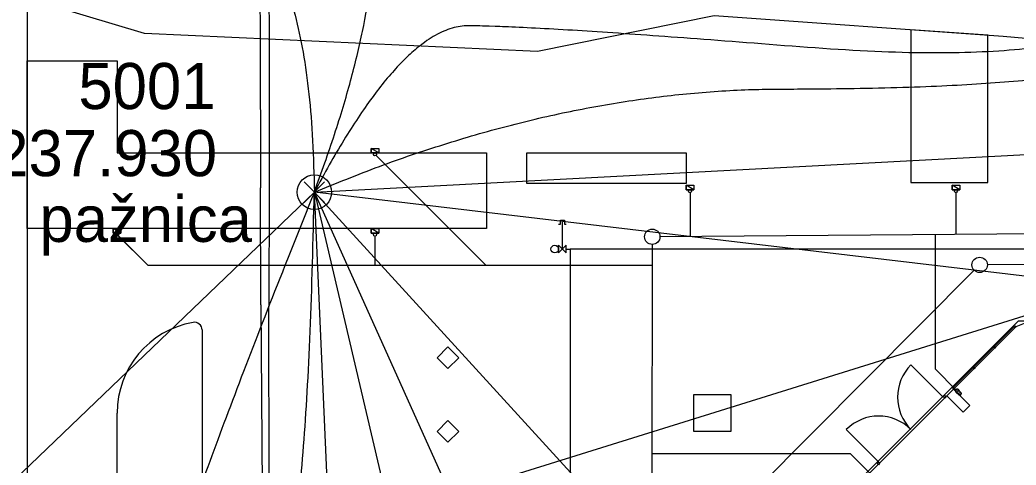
# Model space of a CAD drawing. Extents: x -264090 to -263500, y -1242327 to -1242030.
# Drawn here: x -263959.9 to -263895.1, y -1242096.7 to -1242067.7 of the extents above; entities that cross this region are included whole.
import ezdxf

# ---------------------------------------------------------------- set-up
doc = ezdxf.new("R2010")
doc.units = 0
for name, color, linetype in [('KFA_KOORD_SIT_a_IS_SEDA', 7, 'Continuous'), ('KFA_ZVS_BOD_CISLO', 7, 'Continuous'), ('KFA_ZVS_BOD_SYMBOL', 7, 'Continuous'), ('KFA_ZVS_BOD_VYSKA', 7, 'Continuous'), ('KFA_ZVS_NIVELACIA', 7, 'Continuous'), ('KFA_ZVS_POPIS', 7, 'Continuous'), ('KFA_ZVS_SMERY_A_DLZKY', 7, 'Continuous')]:
    doc.layers.add(name, color=color, linetype=linetype)

msp = doc.modelspace()

# ---------------------------------------------------------------- linework, layer by layer
at = {"layer": 'KFA_KOORD_SIT_a_IS_SEDA'}
for p, q in [((-263959.468, -1242059.534), (-263959.468, -1242179.482)), ((-263944.335, -1242065.473), (-263944.315, -1242068.492)), ((-263943.761, -1242065.469), (-263943.733, -1242068.48)), ((-263944.315, -1242068.492), (-263944.281, -1242078.658)), ((-263943.733, -1242068.48), (-263943.726, -1242078.708)), ((-263896.968, -1242068.731), (-263901.968, -1242068.376)), ((-263901.968, -1242068.376), (-263901.968, -1242074.382)), ((-263896.968, -1242074.382), (-263896.968, -1242068.731)), ((-263959.468, -1242071.382), (-263959.468, -1242070.382)), ((-263959.468, -1242070.382), (-263953.617, -1242070.382)), ((-263953.617, -1242070.382), (-263953.617, -1242076.382)), ((-263959.468, -1242076.382), (-263959.468, -1242071.382)), ((-263901.968, -1242074.382), (-263901.968, -1242078.308)), ((-263896.968, -1242078.308), (-263896.968, -1242074.382)), ((-263959.468, -1242081.307), (-263959.468, -1242076.382)), ((-263953.617, -1242076.382), (-263929.58, -1242076.382)), ((-263937.093, -1242076.382), (-263937.093, -1242076.092)), ((-263937.093, -1242076.092), (-263936.593, -1242076.092)), ((-263936.593, -1242076.382), (-263937.093, -1242076.092)), ((-263936.593, -1242076.382), (-263937.093, -1242076.092)), ((-263937.093, -1242076.092), (-263937.093, -1242076.382)), ((-263936.593, -1242076.382), (-263937.093, -1242076.382)), ((-263937.093, -1242076.382), (-263936.593, -1242076.382)), ((-263936.772, -1242076.553), (-263929.628, -1242083.697)), ((-263936.593, -1242076.092), (-263936.593, -1242076.382)), ((-263929.58, -1242076.382), (-263929.58, -1242081.307)), ((-263926.968, -1242076.382), (-263921.968, -1242076.382)), ((-263926.968, -1242078.382), (-263926.968, -1242076.382)), ((-263926.968, -1242076.382), (-263926.968, -1242076.382)), ((-263921.968, -1242076.382), (-263916.593, -1242076.382)), ((-263916.593, -1242076.382), (-263916.593, -1242078.382)), ((-263921.968, -1242078.382), (-263926.968, -1242078.382)), ((-263916.593, -1242078.382), (-263921.968, -1242078.382)), ((-263916.593, -1242078.777), (-263916.593, -1242078.487)), ((-263916.593, -1242078.487), (-263916.093, -1242078.487)), ((-263916.093, -1242078.777), (-263916.593, -1242078.487)), ((-263916.093, -1242078.777), (-263916.593, -1242078.487)), ((-263916.593, -1242078.487), (-263916.593, -1242078.777)), ((-263916.093, -1242078.487), (-263916.093, -1242078.777)), ((-263901.968, -1242078.308), (-263896.968, -1242078.308)), ((-263899.296, -1242078.777), (-263899.296, -1242078.487)), ((-263899.296, -1242078.487), (-263898.796, -1242078.487)), ((-263898.796, -1242078.777), (-263899.296, -1242078.487)), ((-263898.796, -1242078.777), (-263899.296, -1242078.487)), ((-263899.296, -1242078.487), (-263899.296, -1242078.777)), ((-263898.796, -1242078.487), (-263898.796, -1242078.777)), ((-263944.262, -1242086.274), (-263944.281, -1242078.658)), ((-263943.726, -1242078.708), (-263943.748, -1242086.382)), ((-263916.093, -1242078.777), (-263916.593, -1242078.777)), ((-263916.593, -1242078.777), (-263916.093, -1242078.777)), ((-263916.343, -1242078.977), (-263916.343, -1242081.82)), ((-263898.796, -1242078.777), (-263899.296, -1242078.777)), ((-263899.296, -1242078.777), (-263898.796, -1242078.777)), ((-263899.046, -1242078.977), (-263899.047, -1242081.696)), ((-263924.893, -1242081.015), (-263924.768, -1242081.015)), ((-263924.768, -1242081.015), (-263924.768, -1242080.765)), ((-263924.768, -1242080.765), (-263924.518, -1242080.765)), ((-263924.643, -1242082.64), (-263924.643, -1242080.89)), ((-263924.518, -1242080.765), (-263924.518, -1242081.015)), ((-263924.518, -1242081.015), (-263924.393, -1242081.015)), ((-263953.617, -1242081.307), (-263959.468, -1242081.307)), ((-263953.868, -1242081.597), (-263953.868, -1242081.307)), ((-263953.868, -1242081.307), (-263953.368, -1242081.307)), ((-263953.368, -1242081.597), (-263953.868, -1242081.307)), ((-263953.368, -1242081.597), (-263953.868, -1242081.307)), ((-263953.868, -1242081.307), (-263953.868, -1242081.597)), ((-263953.368, -1242081.597), (-263953.868, -1242081.597)), ((-263953.868, -1242081.597), (-263953.368, -1242081.597)), ((-263953.618, -1242081.697), (-263951.618, -1242083.697)), ((-263929.58, -1242081.307), (-263953.617, -1242081.307)), ((-263953.368, -1242081.307), (-263953.368, -1242081.597)), ((-263937.093, -1242081.597), (-263937.093, -1242081.307)), ((-263937.093, -1242081.307), (-263936.593, -1242081.307)), ((-263936.593, -1242081.597), (-263937.093, -1242081.307)), ((-263936.593, -1242081.597), (-263937.093, -1242081.307)), ((-263937.093, -1242081.307), (-263937.093, -1242081.597)), ((-263936.593, -1242081.597), (-263937.093, -1242081.597)), ((-263937.093, -1242081.597), (-263936.593, -1242081.597)), ((-263936.593, -1242081.307), (-263936.593, -1242081.597)), ((-263872.456, -1242081.505), (-263918.302, -1242081.834)), ((-263900.379, -1242090.456), (-263900.379, -1242081.705)), ((-263953.547, -1242081.768), (-263951.618, -1242083.697)), ((-263936.843, -1242081.797), (-263936.843, -1242083.697)), ((-263924.393, -1242082.39), (-263924.893, -1242082.89)), ((-263924.893, -1242082.89), (-263924.893, -1242082.39)), ((-263924.893, -1242082.39), (-263924.393, -1242082.89)), ((-263924.393, -1242082.89), (-263924.393, -1242082.39)), ((-263918.803, -1242082.338), (-263918.855, -1242106.583)), ((-263924.393, -1242082.64), (-263924.143, -1242082.64)), ((-263788.143, -1242082.64), (-263924.143, -1242082.64)), ((-263924.143, -1242082.64), (-263924.143, -1242185.14)), ((-263853.342, -1242083.478), (-263897, -1242083.666)), ((-263951.618, -1242083.697), (-263918.806, -1242083.697)), ((-263897.853, -1242084.022), (-263922.202, -1242108.463)), ((-263944.262, -1242086.274), (-263944.165, -1242100.884)), ((-263943.732, -1242100.264), (-263943.748, -1242086.382)), ((-263895.135, -1242087.687), (-263894.581, -1242087.457)), ((-263948.093, -1242087.901), (-263948.093, -1242241.458)), ((-263908.663, -1242101.215), (-263895.135, -1242087.687)), ((-263895.258, -1242087.647), (-263896.566, -1242088.955)), ((-263896.548, -1242088.973), (-263895.24, -1242087.665)), ((-263895.273, -1242087.698), (-263895.245, -1242087.67)), ((-263895.202, -1242087.769), (-263895.273, -1242087.698)), ((-263895.24, -1242087.665), (-263895.258, -1242087.647)), ((-263895.245, -1242087.67), (-263895.216, -1242087.641)), ((-263895.216, -1242087.641), (-263895.146, -1242087.712)), ((-263895.146, -1242087.712), (-263895.202, -1242087.769)), ((-263932.8, -1242089.707), (-263932.093, -1242089)), ((-263932.093, -1242089), (-263931.386, -1242089.707)), ((-263932.093, -1242089), (-263932.093, -1242089)), ((-263897.906, -1242090.295), (-263896.598, -1242088.987)), ((-263896.58, -1242089.005), (-263897.888, -1242090.313)), ((-263896.598, -1242088.987), (-263896.58, -1242089.005)), ((-263896.592, -1242089.017), (-263896.564, -1242088.989)), ((-263896.522, -1242089.088), (-263896.592, -1242089.017)), ((-263896.566, -1242088.955), (-263896.548, -1242088.973)), ((-263896.564, -1242088.989), (-263896.536, -1242088.96)), ((-263896.536, -1242088.96), (-263896.465, -1242089.031)), ((-263896.465, -1242089.031), (-263896.522, -1242089.088)), ((-263932.093, -1242090.414), (-263932.8, -1242089.707)), ((-263931.386, -1242089.707), (-263932.093, -1242090.414)), ((-263899.866, -1242092.276), (-263901.97, -1242090.173)), ((-263899.018, -1242091.817), (-263900.379, -1242090.456)), ((-263899.25, -1242091.639), (-263897.942, -1242090.331)), ((-263897.924, -1242090.349), (-263899.232, -1242091.657)), ((-263897.942, -1242090.331), (-263897.924, -1242090.349)), ((-263897.936, -1242090.361), (-263897.908, -1242090.333)), ((-263897.865, -1242090.432), (-263897.936, -1242090.361)), ((-263897.908, -1242090.333), (-263897.88, -1242090.304)), ((-263897.888, -1242090.313), (-263897.906, -1242090.295)), ((-263897.88, -1242090.304), (-263897.809, -1242090.375)), ((-263897.809, -1242090.375), (-263897.865, -1242090.432)), ((-263916.093, -1242092.107), (-263913.693, -1242092.107)), ((-263916.093, -1242094.507), (-263916.093, -1242092.107)), ((-263913.693, -1242092.107), (-263913.693, -1242094.507)), ((-263899.207, -1242091.764), (-263899.631, -1242092.188)), ((-263899.255, -1242091.68), (-263899.227, -1242091.652)), ((-263899.185, -1242091.751), (-263899.255, -1242091.68)), ((-263899.232, -1242091.657), (-263899.25, -1242091.639)), ((-263899.227, -1242091.652), (-263899.199, -1242091.624)), ((-263898.147, -1242092.824), (-263899.207, -1242091.764)), ((-263899.199, -1242091.624), (-263899.128, -1242091.694)), ((-263899.128, -1242091.694), (-263899.185, -1242091.751)), ((-263898.969, -1242092.031), (-263899.047, -1242091.953)), ((-263899.047, -1242091.953), (-263898.969, -1242092.031)), ((-263898.949, -1242092.031), (-263898.969, -1242092.031)), ((-263898.861, -1242092.119), (-263898.949, -1242092.031)), ((-263898.804, -1242091.866), (-263898.882, -1242091.787)), ((-263898.804, -1242091.885), (-263898.804, -1242091.866)), ((-263898.715, -1242091.974), (-263898.804, -1242091.885)), ((-263899.849, -1242092.259), (-263899.866, -1242092.276)), ((-263899.764, -1242092.174), (-263899.849, -1242092.259)), ((-263899.849, -1242092.259), (-263899.764, -1242092.344)), ((-263899.679, -1242092.259), (-263899.764, -1242092.174)), ((-263899.764, -1242092.344), (-263899.679, -1242092.259)), ((-263899.631, -1242092.188), (-263898.571, -1242093.249)), ((-263953.617, -1242244.458), (-263953.617, -1242093.307)), ((-263898.571, -1242093.249), (-263898.147, -1242092.824)), ((-263932.8, -1242094.507), (-263932.093, -1242093.8)), ((-263932.093, -1242093.8), (-263931.386, -1242094.507)), ((-263932.093, -1242093.8), (-263932.093, -1242093.8)), ((-263932.093, -1242095.214), (-263932.8, -1242094.507)), ((-263931.386, -1242094.507), (-263932.093, -1242095.214)), ((-263913.693, -1242094.507), (-263916.093, -1242094.507)), ((-263904.074, -1242096.484), (-263906.177, -1242094.38)), ((-263905.894, -1242095.971), (-263918.832, -1242095.971)), ((-263904.533, -1242097.332), (-263905.894, -1242095.971)), ((-263904.176, -1242096.586), (-263904.091, -1242096.501)), ((-263904.091, -1242096.671), (-263904.176, -1242096.586)), ((-263904.091, -1242096.501), (-263904.074, -1242096.484)), ((-263904.091, -1242096.501), (-263904.006, -1242096.586)), ((-263904.006, -1242096.586), (-263904.091, -1242096.671))]:
    msp.add_line(p, q, dxfattribs=at)
for points in [[(-263864.521, -1242071.581), (-263895.971, -1242068.802), (-263914.777, -1242067.467), (-263926.271, -1242069.784), (-263951.845, -1242068.605), (-263959.611, -1242066.277)], [(-263794.893, -1242227.382), (-263808.968, -1242241.457), (-263894.968, -1242241.457), (-263909.043, -1242227.382), (-263909.043, -1242196.333), (-263914.143, -1242196.333), (-263914.143, -1242132.433), (-263909.043, -1242132.433), (-263909.043, -1242101.382), (-263894.968, -1242087.307), (-263808.968, -1242087.307), (-263794.893, -1242101.382), (-263794.893, -1242227.382)]]:
    msp.add_lwpolyline(points, dxfattribs=at)
for centre, radius in [((-263936.843, -1242076.482), 0.1), ((-263916.343, -1242078.877), 0.1), ((-263899.046, -1242078.877), 0.1), ((-263953.618, -1242081.697), 0.1), ((-263936.843, -1242081.697), 0.1), ((-263918.802, -1242081.838), 0.5), ((-263925.143, -1242082.64), 0.25), ((-263897.5, -1242083.668), 0.5), ((-263898.965, -1242091.87), 0.075), ((-263898.788, -1242092.047), 0.075)]:
    msp.add_circle(centre, radius, dxfattribs=at)
for centre, radius, start, end in [((-263947.634, -1242093.3), 5.983, 100.0694, 180.06602), ((-263948.593, -1242087.901), 0.5, 0, 100.0694), ((-263899.866, -1242092.276), 2.975, 135.00007, 225.00006), ((-263898.965, -1242091.87), 0.117, 45, 225), ((-263898.788, -1242092.047), 0.103, 225, 45), ((-263904.074, -1242096.484), 2.975, 44.99994, 134.99992)]:
    msp.add_arc(centre, radius, start, end, dxfattribs=at)
at = {"layer": 'KFA_ZVS_BOD_SYMBOL'}
for p, q in [((-263941.451, -1242079.601), (-263940.125, -1242078.275)), ((-263940.125, -1242079.601), (-263941.451, -1242078.275))]:
    msp.add_line(p, q, dxfattribs=at)
msp.add_circle((-263940.788, -1242078.938), 1.125, dxfattribs=at)
at = {"layer": 'KFA_ZVS_NIVELACIA'}
for points in [[(-263940.788, -1242078.938), (-263934.156, -1242061.096), (-263943.396, -1242047.979), (-263966.375, -1242038.897), (-263966.375, -1242044.573)], [(-263966.375, -1242044.573), (-263958.148, -1242047.979), (-263963.822, -1242056.777), (-263950.488, -1242056.777), (-263940.964, -1242064.52), (-263940.788, -1242078.938)], [(-263854.005, -1242074.334), (-263858.192, -1242065.861), (-263863.591, -1242056.689), (-263882.165, -1242064.383), (-263892.212, -1242070.833), (-263926.489, -1242068.112), (-263935.058, -1242068.112), (-263940.788, -1242078.938)], [(-263940.788, -1242078.938), (-263924.876, -1242072.224), (-263895.483, -1242072.224), (-263880.684, -1242069.371), (-263870.098, -1242060.864), (-263861.313, -1242065.002), (-263856.49, -1242070.133), (-263854.005, -1242074.334)], [(-263940.788, -1242078.938), (-263950.124, -1242102.026), (-263955.973, -1242123.929), (-263955.973, -1242134.13), (-263943.376, -1242149.689), (-263946.118, -1242158.004), (-263936.802, -1242167.947)], [(-263936.802, -1242167.947), (-263938.18, -1242161.645), (-263941.069, -1242151.603), (-263943.851, -1242126.263), (-263950.707, -1242125.062), (-263946.422, -1242113.061), (-263941.281, -1242104.232), (-263940.788, -1242078.938)]]:
    msp.add_open_spline(points, degree=2, dxfattribs=at)
at = {"layer": 'KFA_ZVS_SMERY_A_DLZKY'}
for p, q in [((-263854.005, -1242074.334), (-263975.491, -1242112.207)), ((-263940.788, -1242078.938), (-263854.005, -1242074.334)), ((-263940.788, -1242078.938), (-263975.491, -1242112.207)), ((-263936.802, -1242167.947), (-263940.788, -1242078.938)), ((-263779.166, -1242098.021), (-263940.788, -1242078.938)), ((-263786.209, -1242248.09), (-263940.788, -1242078.938)), ((-263858.267, -1242262.294), (-263940.788, -1242078.938)), ((-263940.788, -1242078.938), (-263916.904, -1242180.641))]:
    msp.add_line(p, q, dxfattribs=at)

# ---------------------------------------------------------------- texts
at = {"layer": 'KFA_ZVS_BOD_CISLO'}
msp.add_text('5001', height=3, dxfattribs=at).set_placement((-263956.142, -1242073.531))
at = {"layer": 'KFA_ZVS_BOD_VYSKA'}
msp.add_text('237.930', height=3, dxfattribs=at).set_placement((-263961.619, -1242077.897))
at = {"layer": 'KFA_ZVS_POPIS'}
msp.add_text('pažnica', height=3, dxfattribs=at).set_placement((-263958.675, -1242082.173))

doc.saveas('drawing.dxf')
